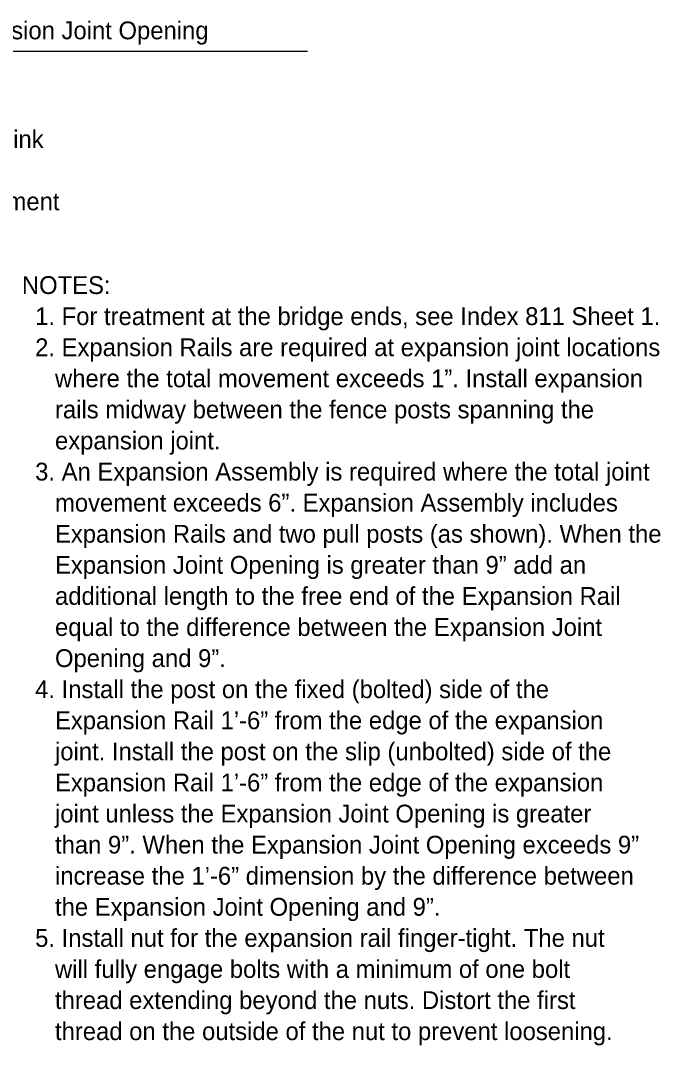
# Model space of a CAD drawing. Extents: x 0.4 to 38.5, y 1.2 to 25.4.
# Drawn here: x 31.18 to 38.43, y 13.83 to 25.44 of the extents above; entities that cross this region are included whole.
import ezdxf

# ---------------------------------------------------------------- set-up
doc = ezdxf.new("R2010")
doc.units = 0
doc.layers.add('Dimension', color=7, linetype='Continuous')
doc.layers.add('TextStructures', color=7, linetype='Continuous')

msp = doc.modelspace()

# ---------------------------------------------------------------- linework, layer by layer
at = {"layer": 'Dimension'}
msp.add_line((25.53, 25.088), (34.433, 25.088), dxfattribs=at)

# ---------------------------------------------------------------- texts
for s, p in [('Bulge Chain Link ', (29.408, 23.991)), ('for joint movement', (29.408, 23.287)), ('NOTES:', (31.2, 22.339)), ('  1. For treatment at the bridge ends, see Index 811 Sheet 1.', (31.2, 21.987)), ('  2. Expansion Rails are required at expansion joint locations', (31.2, 21.635)), ('     where the total movement exceeds 1”. Install expansion', (31.2, 21.283)), ('     rails midway between the fence posts spanning the', (31.2, 20.931)), ('     expansion joint.  ', (31.2, 20.579)), ('  3. An Expansion Assembly is required where the total joint', (31.2, 20.227)), ('     movement exceeds 6”. Expansion Assembly includes', (31.2, 19.875)), ('     Expansion Rails and two pull posts (as shown). When the', (31.2, 19.523)), ('     Expansion Joint Opening is greater than 9” add an', (31.2, 19.171)), ('     additional length to the free end of the Expansion Rail', (31.2, 18.819)), ('     equal to the difference between the Expansion Joint', (31.2, 18.467)), ('     Opening and 9”. ', (31.2, 18.115)), ('  4. Install the post on the fixed (bolted) side of the', (31.2, 17.763)), ('     Expansion Rail 1’-6” from the edge of the expansion', (31.2, 17.411)), ('     joint. Install the post on the slip (unbolted) side of the', (31.2, 17.059)), ('     Expansion Rail 1’-6” from the edge of the expansion', (31.2, 16.707)), ('     joint unless the Expansion Joint Opening is greater', (31.2, 16.355)), ('     than 9”. When the Expansion Joint Opening exceeds 9”', (31.2, 16.003)), ('     increase the 1’-6” dimension by the difference between', (31.2, 15.651)), ('     the Expansion Joint Opening and 9”. ', (31.2, 15.299)), ('  5. Install nut for the expansion rail finger-tight. The nut', (31.2, 14.947)), ('     will fully engage bolts with a minimum of one bolt', (31.2, 14.595)), ('     thread extending beyond the nuts. Distort the first', (31.2, 14.243)), ('     thread on the outside of the nut to prevent loosening.   ', (31.2, 13.891))]:
    msp.add_text(s, height=0.2016, dxfattribs=at).set_placement(p)
at = {"layer": 'TextStructures'}
msp.add_text('3\'-0" (Min.) + Expansion Joint Opening', height=0.2016, dxfattribs=at).set_placement((28.707, 25.223))

doc.saveas('drawing.dxf')
